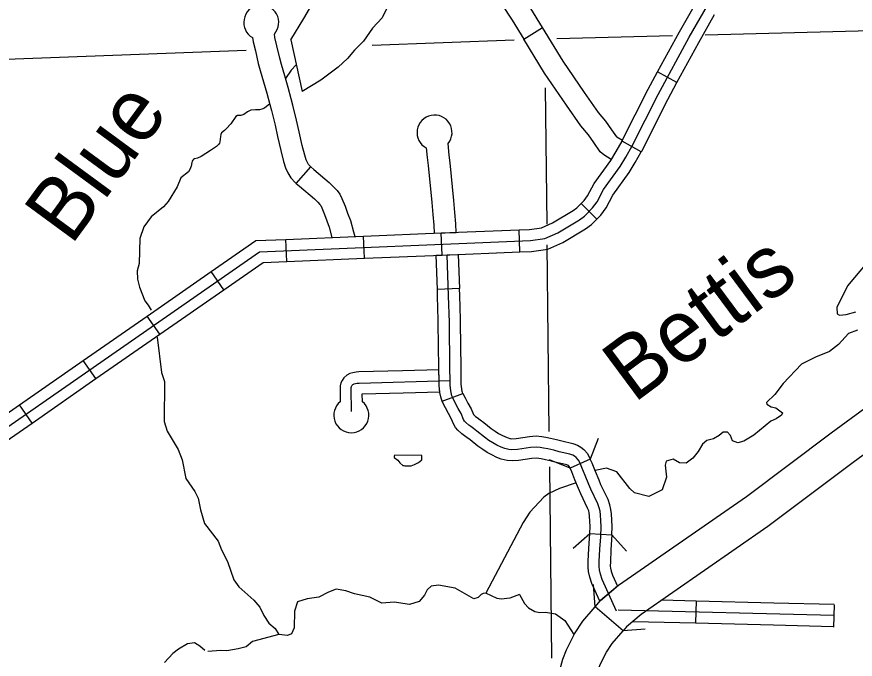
# Model space of a CAD drawing. Extents: x 1212896 to 1368412, y 378476 to 478763.
# Drawn here: x 1260272 to 1265961, y 391011 to 395366 of the extents above; entities that cross this region are included whole.
import ezdxf

# ---------------------------------------------------------------- set-up
doc = ezdxf.new("R2010")
doc.units = 0
for name, color, linetype in [('Level 10', 7, 'Continuous'), ('Level 31', 7, 'Continuous'), ('Level 32', 7, 'Continuous'), ('Level 35', 7, 'Continuous'), ('Level 37', 7, 'Continuous'), ('Level 38', 7, 'Continuous'), ('Level 45', 7, 'Continuous'), ('Level 5', 7, 'Continuous')]:
    doc.layers.add(name, color=color, linetype=linetype)

msp = doc.modelspace()

# ---------------------------------------------------------------- linework, layer by layer
at = {"layer": 'Level 10'}
msp.add_line((1264386.4, 391203.7), (1264196.6, 391366.5), dxfattribs=at)
for points in [[(1264196.6, 391366.5), (1264233, 391408.6), (1264354.8, 391512.8), (1265222.9, 392114.5), (1265798, 392544.8), (1267016.5, 393438.5), (1267604.8, 393882.3), (1267943.6, 394159.6), (1268436, 394612.2), (1271341.9, 397349.4)], [(1271515.3, 397169.3), (1268606.3, 394429.2), (1268107.5, 393970.7), (1267759.3, 393685.7), (1267165.7, 393237.9), (1265946.8, 392343.9), (1265369, 391911.6), (1264507.7, 391314.5), (1264409.8, 391230.9), (1264385.8, 391203)], [(1263932.2, 390847.3), (1263977.1, 391010.2), (1264001.5, 391075.5), (1264056.8, 391183.9), (1264112.6, 391269.3), (1264196.6, 391366.5)], [(1264173.2, 390780.7), (1264215.2, 390933.1), (1264230.7, 390974.8), (1264273.4, 391058.3), (1264312.7, 391118.5), (1264386.4, 391203.7)]]:
    msp.add_lwpolyline(points, dxfattribs=at)
at = {"layer": 'Level 31'}
for p, q in [((1263712.3, 395214.3), (1263840.2, 395292.6)), ((1263840.2, 395292.6), (1263840.2, 395292.6)), ((1262167.7, 394236.1), (1262266.5, 394348.9)), ((1262266.5, 394348.9), (1262266.5, 394348.9)), ((1263103.3, 393898.6), (1263253.2, 393904.7)), ((1263158.9, 392759.3), (1263299.5, 392811.5)), ((1263617.8, 392507.3), (1263617.8, 392507.3)), ((1264163.2, 392367.6), (1264025.9, 392307.2))]:
    msp.add_line(p, q, dxfattribs=at)
for points in [[(1263840.2, 395292.6), (1263760.1, 395423.5), (1263554.8, 395739.1)], [(1263428.3, 395658.4), (1263633.2, 395343.5), (1263712.3, 395214.3)], [(1262134.1, 394810.6), (1262113.4, 394887.5), (1262090.7, 394966.8), (1262068.3, 395043.8), (1262056.1, 395086.5), (1262037.2, 395170.2), (1262023.3, 395225.7), (1262019.5, 395249.2)], [(1264125.1, 394853), (1263979.4, 395065.1), (1263840.2, 395292.6)], [(1261871.5, 395224.8), (1261876.2, 395195.5), (1261891.2, 395135.5), (1261910.7, 395049.3), (1261924.2, 395002.2), (1261946.6, 394925.2), (1261968.9, 394847.3), (1261989.3, 394771.5)], [(1264001.5, 394768.1), (1263853.5, 394983.4), (1263712.3, 395214.3)], [(1264380.9, 394527.3), (1264344.2, 394551.2), (1264342.7, 394552.4), (1264310, 394600.7), (1264268.6, 394657.5), (1264218, 394717.8), (1264125.1, 394853)], [(1262266.5, 394348.9), (1262265, 394350.3), (1262252.1, 394364.1), (1262244.2, 394377.4), (1262236.2, 394395.5), (1262225.3, 394428.2), (1262208.7, 394493.4), (1262188.1, 394586.9), (1262170.3, 394666.3), (1262145.8, 394767.3), (1262134.1, 394810.6)], [(1261989.3, 394771.5), (1262000.5, 394730.1), (1262024.2, 394632.2), (1262041.6, 394554.4), (1262062.7, 394458.7), (1262081.3, 394385.9), (1262096.1, 394341.7), (1262110.6, 394308.5), (1262131.5, 394273.6), (1262160.3, 394242.5), (1262167.7, 394236.1)], [(1264305, 394397.7), (1264254.9, 394430.3), (1264230.4, 394450.7), (1264187.2, 394514.4), (1264150.4, 394565.1), (1264098.5, 394626.9), (1264001.5, 394768.1)], [(1263244.6, 394039), (1263237.9, 394121.5), (1263212.6, 394375.5), (1263205.1, 394427.8), (1263198.8, 394506.9)], [(1263050.7, 394477), (1263056, 394411.2), (1263063.7, 394357.4), (1263088.5, 394108), (1263095.1, 394026.9)], [(1262266.5, 394348.9), (1262287.2, 394330.8), (1262390.8, 394243.3), (1262421.4, 394214.5), (1262445.9, 394188), (1262463.2, 394163.2), (1262477.8, 394134), (1262500.4, 394081.8), (1262517, 394035.2), (1262535.9, 393985.4), (1262555.6, 393908.1), (1262565.7, 393876.5)], [(1262167.7, 394236.1), (1262189.4, 394217.1), (1262290.9, 394131.3), (1262314.8, 394108.9), (1262328.8, 394093.7), (1262333.9, 394086.3), (1262341.8, 394070.6), (1262360.8, 394026.7), (1262376.2, 393983.4), (1262392.6, 393940.2), (1262410.5, 393870.1)], [(1263095.1, 394026.9), (1263101.1, 393952.9), (1263103.3, 393898.6)], [(1263253.2, 393904.7), (1263250.9, 393962), (1263244.6, 394039)], [(1263117.5, 393749), (1263267.3, 393755.2)], [(1263125.6, 393517.5), (1263117.5, 393749)], [(1264341.6, 391337.1), (1264244.6, 391552.3), (1264232.5, 391587.8), (1264226.3, 391616.9), (1264224, 391638.9), (1264224.7, 391672.8), (1264227.9, 391757.5), (1264234, 391839.9), (1264236.8, 391911.6), (1264235.4, 391949.2), (1264232.5, 391989.7), (1264229.7, 392014.5), (1264224.7, 392037.1), (1264214.8, 392064.3), (1264167.3, 392163.3), (1264153.8, 392195.6), (1264128.9, 392256), (1264106.6, 392310.3), (1264093.8, 392339.1), (1264082.6, 392361.4), (1264067.2, 392378.1), (1264056.6, 392386.6), (1264045.2, 392393.7), (1264023.9, 392400.1), (1263953, 392417.9), (1263916.8, 392427.1), (1263876.3, 392436.3), (1263845.8, 392442.7), (1263823.8, 392447), (1263796.8, 392449.3), (1263758.5, 392446.3), (1263669.1, 392433.5), (1263631.5, 392430.7), (1263610, 392431.7), (1263582.5, 392439.2), (1263557.7, 392448.4), (1263528.6, 392462.6), (1263502.4, 392476.8), (1263475.4, 392493.9), (1263444.9, 392515.9), (1263394.5, 392556.3), (1263371.8, 392574.8), (1263353.3, 392587.6), (1263338.6, 392597.9), (1263317.9, 392615.5), (1263310.8, 392624.5), (1263303.5, 392636.2), (1263286.6, 392675.6), (1263266.8, 392711.3), (1263247.6, 392748.1), (1263230, 392783.2), (1263224.9, 392797.1), (1263222.1, 392807.2), (1263217.3, 392831.1), (1263212.8, 392869.5), (1263212.1, 392900), (1263211.4, 392983.8), (1263207.2, 393292.7), (1263202.2, 393473.8), (1263192.4, 393752.1)], [(1263267.3, 393755.2), (1263275.5, 393523.7)], [(1263275.5, 393523.7), (1263125.6, 393517.5)], [(1263131.7, 393309.4), (1263127.2, 393471.4), (1263125.6, 393517.5)], [(1263281.6, 393313.5), (1263277.2, 393476.1), (1263275.5, 393523.7)], [(1263158.9, 392759.3), (1263153.5, 392773.8), (1263149.1, 392789.7), (1263143.1, 392819.5), (1263137.9, 392864.3), (1263137.1, 392898.8), (1263136.4, 392983), (1263132.2, 393291.2), (1263131.7, 393309.4)], [(1263299.5, 392811.5), (1263296.3, 392820.3), (1263295, 392824.7), (1263291.4, 392842.8), (1263287.7, 392874.7), (1263287.1, 392901.2), (1263286.4, 392984.6), (1263282.1, 393294.2), (1263281.6, 393313.5)], [(1262889.2, 392966.4), (1262592.4, 392958.4), (1262573.7, 392957), (1262551.3, 392953.3), (1262532.5, 392947), (1262510.6, 392936.8), (1262490, 392918), (1262479.1, 392900.9), (1262471.3, 392884.2), (1262466.7, 392863.9), (1262465.8, 392844.8), (1262466.9, 392756.4)], [(1263136.5, 392973), (1262889.2, 392966.4)], [(1263142.7, 392823.1), (1263137.9, 392864.3), (1263137.1, 392898.8), (1263136.5, 392973)], [(1262542.6, 392689.5), (1262540.8, 392843.6), (1262541.3, 392853.8), (1262542.6, 392859.6), (1262545.1, 392864.8), (1262547.9, 392869.3), (1262552.8, 392873.7), (1262560.3, 392877.3), (1262569.4, 392880.3), (1262582.6, 392882.5), (1262596.1, 392883.4), (1263212.1, 392900)], [(1262616.9, 392756.5), (1262616.3, 392809), (1262893.3, 392816.4)], [(1262893.3, 392816.4), (1263142.7, 392823.1)], [(1263299.5, 392811.5), (1263314.4, 392782.2), (1263332.8, 392746.9), (1263354.1, 392708.7), (1263370.2, 392670.9), (1263372.2, 392667.7), (1263384.4, 392657.4), (1263396.2, 392649.1), (1263416.9, 392634.8), (1263441.6, 392614.7), (1263490.3, 392575.6), (1263517.4, 392556), (1263540.3, 392541.6), (1263562.9, 392529.3), (1263587.3, 392517.4), (1263605.5, 392510.7), (1263617.8, 392507.3)], [(1263578.5, 392362.6), (1263559.6, 392367.7), (1263528.1, 392379.4), (1263494.3, 392395.9), (1263464.4, 392412.1), (1263433.4, 392431.7), (1263399.4, 392456.2), (1263347.3, 392498), (1263326.7, 392514.8), (1263310.5, 392526), (1263292.8, 392538.4), (1263263.5, 392563.2), (1263249.2, 392581.5), (1263236.8, 392601.5), (1263219.2, 392642.6), (1263200.7, 392675.7), (1263180.8, 392714), (1263161.1, 392753.3), (1263158.9, 392759.3)], [(1263617.8, 392507.3), (1263621.8, 392506.2), (1263630.5, 392505.8), (1263661, 392508.1), (1263750.3, 392520.9), (1263797.1, 392524.5), (1263834.2, 392521.4), (1263860.6, 392516.2), (1263892.4, 392509.6), (1263934.4, 392500), (1263971.3, 392490.6), (1264043.8, 392472.5), (1264076.4, 392462.7), (1264100, 392447.9), (1264118.5, 392433.2), (1264145, 392404.5), (1264163.2, 392367.6)], [(1264025.9, 392307.2), (1264020.3, 392318.3), (1264016, 392323.1), (1264013.7, 392324.9), (1264004, 392327.8), (1263934.6, 392345.2), (1263899.2, 392354.2), (1263860.3, 392363.1), (1263831, 392369.2), (1263813.5, 392372.6), (1263796.6, 392374), (1263766.8, 392371.7), (1263677.3, 392358.9), (1263632.5, 392355.5), (1263598.2, 392357.2), (1263578.5, 392362.6)], [(1264309.6, 391854.7), (1264311.9, 391911.5), (1264310.3, 391953.3), (1264307.2, 391996.6), (1264303.8, 392026.9), (1264296.9, 392058.1), (1264284, 392093.4), (1264235.7, 392194), (1264223.1, 392224.3), (1264198.3, 392284.5), (1264175.5, 392339.8), (1264163.2, 392367.6)], [(1264159.8, 391863.2), (1264161.7, 391911.8), (1264160.4, 391945.3), (1264157.8, 391983), (1264155.5, 392002.4), (1264152.5, 392016.2), (1264145.5, 392035.2), (1264098.7, 392132.8), (1264084.4, 392167.1), (1264059.5, 392227.6), (1264037.5, 392281), (1264025.9, 392307.2)], [(1264229.1, 391404.1), (1264174.8, 391524.7), (1264160.1, 391567.8), (1264152.2, 391605.1), (1264148.9, 391635.8), (1264149.8, 391675), (1264153, 391761.6), (1264159.8, 391863.2)], [(1264159.8, 391863.2), (1264309.6, 391854.7)], [(1264309.6, 391854.7), (1264302.8, 391753.3), (1264299.7, 391670.6), (1264299.1, 391642), (1264300.5, 391628.7), (1264305, 391607.7), (1264314.5, 391579.8), (1264347.5, 391506.5)], [(1264347.5, 391506.5), (1264233, 391408.6), (1264229.1, 391404.1)]]:
    msp.add_lwpolyline(points, dxfattribs=at)
for centre, start, end in [((1261930.5, 395327.7), 318.5685, 240.1612), ((1263106.6, 394581.7), 320.9445, 241.8735), ((1262542, 392664.5), 129.2679, 50.856)]:
    msp.add_arc(centre, 118.7, start, end, dxfattribs=at)
at = {"layer": 'Level 32'}
for p, q in [((1264751.3, 394920.4), (1264619.6, 394992.1)), ((1264509.5, 394449.8), (1264378.9, 394523.5)), ((1264207.6, 393994.9), (1264101.2, 394100.7)), ((1262630.7, 393729), (1262624.6, 393878.9)), ((1263158.3, 393750.7), (1263152.1, 393900.6)), ((1263685.8, 393772.4), (1263679.7, 393922.2)), ((1262103.2, 393707.4), (1262097, 393857.2)), ((1261676.3, 393515.1), (1261590.7, 393638.3)), ((1261242.5, 393214), (1261157, 393337.2)), ((1260808.8, 392912.9), (1260723.3, 393036.1)), ((1260375.1, 392611.8), (1260289.5, 392735))]:
    msp.add_line(p, q, dxfattribs=at)
for points in [[(1259971.3, 392421.1), (1261919.5, 393773.5), (1263757.6, 393849), (1263854.1, 393862.3), (1263943, 393901.2), (1264089.6, 393988.6), (1264123.1, 394014.3), (1264179.1, 394070.7), (1264209.7, 394110.8), (1264253.9, 394195.4), (1264365.6, 394350.5), (1264405.3, 394415), (1264447.9, 394490.5), (1264623.2, 394839), (1264835.1, 395227.9), (1264983.4, 395488.6)], [(1264619.6, 394992.1), (1264768.4, 395265.1), (1264876.4, 395455)], [(1264751.3, 394920.4), (1264899.4, 395192.1), (1265006.8, 395380.9)], [(1264378.9, 394523.5), (1264380.5, 394526.4), (1264555.5, 394874.5), (1264619.6, 394992.1)], [(1264509.5, 394449.8), (1264512.9, 394455.9), (1264688.4, 394804.9), (1264751.3, 394920.4)], [(1264101.2, 394100.7), (1264121.4, 394121), (1264145, 394151.9), (1264188.7, 394235.6), (1264302, 394392.9), (1264339.5, 394453.7), (1264378.9, 394523.5)], [(1264207.6, 393994.9), (1264234.7, 394022.2), (1264272.1, 394071.1), (1264316.7, 394156.7), (1264426.9, 394309.6), (1264468.7, 394377.6), (1264509.5, 394449.8)], [(1263679.7, 393922.2), (1263750.8, 393925.2), (1263833.2, 393936.5), (1263907.9, 393969.2), (1264046.6, 394052), (1264072.5, 394071.8), (1264101.2, 394100.7)], [(1263685.8, 393772.4), (1263764.1, 393775.6), (1263874.3, 393790.7), (1263976.7, 393835.6), (1264130.9, 393927.6), (1264171.8, 393958.9), (1264207.6, 393994.9)], [(1262097, 393857.2), (1262624.6, 393878.9)], [(1262624.6, 393878.9), (1263152.1, 393900.6)], [(1263152.1, 393900.6), (1263679.7, 393922.2)], [(1261590.7, 393638.3), (1261894.2, 393848.9), (1262097, 393857.2)], [(1263158.3, 393750.7), (1263685.8, 393772.4)], [(1261676.3, 393515.1), (1261943.9, 393700.8), (1262103.2, 393707.4)], [(1262103.2, 393707.4), (1262630.7, 393729)], [(1262630.7, 393729), (1263158.3, 393750.7)], [(1261157, 393337.2), (1261590.7, 393638.3)], [(1261242.5, 393214), (1261676.3, 393515.1)], [(1260723.3, 393036.1), (1261157, 393337.2)], [(1260808.8, 392912.9), (1261242.5, 393214)], [(1260289.5, 392735), (1260723.3, 393036.1)], [(1260375.1, 392611.8), (1260808.8, 392912.9)], [(1259879.5, 392450.8), (1259884.7, 392452.1), (1259907.3, 392467.9), (1259925.7, 392482.5), (1260289.5, 392735)], [(1259914.5, 392305), (1259947.4, 392312.8), (1259996.9, 392347.5), (1260015.2, 392361.9), (1260375.1, 392611.8)]]:
    msp.add_lwpolyline(points, dxfattribs=at)
at = {"layer": 'Level 35'}
for points in [[(1262131.3, 395210.5), (1262220.5, 395355), (1262273.2, 395447.3), (1262334.7, 395667), (1262536.7, 395750.5), (1262576.2, 395737.3), (1262607, 395728.5), (1262642.1, 395746.1), (1262729.9, 395772.5), (1262809, 395798.8), (1262839.7, 395825.2), (1262861.7, 395856), (1262927.6, 395917.5), (1262971.5, 395965.8), (1262997.8, 395987.8), (1263028.6, 395996.6), (1263072.3, 395991.4), (1263098.4, 395983.4)], [(1263252.1, 395680.2), (1263244.1, 395664.5), (1263223.9, 395649.3), (1263182.3, 395627.5), (1263085.6, 395601.1), (1263024.2, 395587.9), (1262962.7, 395548.4), (1262901.2, 395517.6), (1262817.8, 395469.3), (1262787, 395434.1), (1262751.9, 395359.4), (1262686, 395289.1), (1262624.5, 395201.2), (1262563.1, 395139.7), (1262514.8, 395082.6), (1262453.3, 395025.4), (1262334.7, 394937.5), (1262207.4, 394858.9)], [(1262131.3, 395210.5), (1262207.4, 394858.9)], [(1262167.9, 395041.2), (1262134.1, 395005.3), (1262096.3, 394947.3)], [(1261988.3, 394775.2), (1261952, 394745.7), (1261935.2, 394740.1), (1261918.7, 394736.2), (1261892.5, 394736.2), (1261859.7, 394733.6), (1261837.9, 394721.1), (1261813.5, 394703.7), (1261792.3, 394697.1), (1261770.6, 394696.1), (1261758.1, 394689.5), (1261723.5, 394640.9), (1261692.6, 394607.6), (1261680.7, 394595.7), (1261661.6, 394579), (1261657, 394567.7), (1261654.5, 394555.2), (1261652.1, 394536.1), (1261649.7, 394519.5), (1261646.7, 394509.6), (1261641.2, 394500.3), (1261625.9, 394486.1), (1261585.5, 394459.9), (1261523.3, 394419.8), (1261497.4, 394407.5), (1261478.2, 394404.1), (1261471.7, 394399.7), (1261466.8, 394394.8), (1261462.5, 394386.7), (1261459.2, 394377.4), (1261454.3, 394352.4), (1261446.2, 394330.7), (1261436.8, 394314.4)], [(1261436.8, 394314.4), (1261385.8, 394274.3), (1261359.8, 394214.3), (1261299.1, 394115), (1261268.4, 394077.9), (1261182.7, 394008.9), (1261133, 393941.1), (1261105.7, 393862), (1261101.4, 393692.6), (1261089, 393644.1), (1261090.9, 393587.1), (1261104.7, 393532.4), (1261139.8, 393440.5), (1261163.8, 393410.2), (1261182.9, 393376.8)], [(1266039.4, 393697.8), (1265908.6, 393542.1), (1265835.5, 393396.4), (1265839, 393353.5), (1265854.3, 393343), (1265899.1, 393348.5), (1265964.5, 393366.7)], [(1261225.1, 393194.3), (1261253.1, 392954.5), (1261273.1, 392894.1), (1261271.2, 392623.5), (1261291.5, 392556.1), (1261366.6, 392433.4), (1261395, 392362.3), (1261419.2, 392236.9), (1261480.2, 392146.8), (1261502.7, 392102.5), (1261518.3, 392022.9), (1261546.4, 391930.7), (1261638.5, 391810.6), (1261660.4, 391753.2), (1261701, 391673.5), (1261745.2, 391548.8), (1261778.8, 391500.8), (1261879.8, 391412.1), (1261920.4, 391364.4), (1261947.3, 391307.2), (1261982, 391255.3), (1262024.2, 391219.7), (1262049.6, 391179.5)], [(1265976.7, 393240.9), (1265915.8, 393219.4), (1265847, 393144.4), (1265786.6, 393097.2), (1265690.9, 393058.9), (1265597.5, 393011.7), (1265473, 392879.2), (1265415.4, 392806.1)], [(1265415.4, 392806.1), (1265359.3, 392751.1), (1265360.7, 392740.2), (1265390.3, 392722.1), (1265421.5, 392714.2), (1265466.6, 392681.7), (1265461.2, 392665.5), (1265425, 392640.2), (1265387.6, 392623.9), (1265272.8, 392529.8), (1265205.9, 392490.1), (1265165.5, 392478.1), (1265128.1, 392491.9), (1265115.8, 392528.5), (1265095.3, 392549.7), (1265065.1, 392549.8), (1265036.9, 392526.8), (1264998.6, 392505.5), (1264953.1, 392492.9), (1264924.9, 392468.9), (1264894.6, 392418.8), (1264858.1, 392373.5), (1264813.3, 392340.1), (1264769.1, 392342.4), (1264726.4, 392366), (1264678.8, 392354.4), (1264670.7, 392326.1), (1264681.4, 392245.3), (1264650.4, 392158.1), (1264559.9, 392113.9), (1264463, 392139.7), (1264431, 392168.7), (1264344.3, 392280.9), (1264272.4, 392306.5), (1264195.5, 392291.2)], [(1263021.1, 392391.3), (1262835.3, 392394.2), (1262833.7, 392391), (1262832.8, 392387.3), (1262832.4, 392382.3), (1262833.5, 392378.1), (1262856.6, 392360), (1262871.3, 392343.1), (1262891.6, 392325.2), (1262897.3, 392323.4), (1262904.5, 392322.7), (1262947.1, 392322.6), (1262959.9, 392325.9), (1262970.9, 392330.5), (1262984, 392336.8), (1262998.1, 392345), (1263021.1, 392362.2), (1263021.1, 392391.3)], [(1264068, 392206.9), (1263954.2, 392167.5), (1263882.3, 392134), (1263848.2, 392108.8), (1263753.6, 392008.4), (1263709, 391936.8), (1263454.9, 391459.6)], [(1263682.2, 391450.3), (1263682.2, 391450.3), (1263618, 391425.1), (1263558.3, 391418.1), (1263531.1, 391422.1), (1263454.9, 391459.6), (1263436, 391457), (1263422.2, 391449.5), (1263402.9, 391428.8), (1263374.2, 391419.8), (1263246.9, 391491.6), (1263133.1, 391513.8), (1263083.4, 391507.1), (1263057.2, 391482.2), (1263038.5, 391444.5), (1263001.9, 391402.2), (1262937.6, 391382.9), (1262833.1, 391397.4), (1262748.3, 391390.5), (1262667, 391430.8), (1262563.3, 391453.4), (1262505.7, 391475.5), (1262439.4, 391485.3), (1262387.8, 391465.6), (1262320.8, 391431.2), (1262242.5, 391419.4), (1262176.1, 391400.1), (1262155.3, 391336.3), (1262155, 391224.1), (1262136.5, 391182.4), (1262109.8, 391171.5), (1262049.6, 391179.5), (1261872.3, 391130.4), (1261827.5, 391094.8), (1261773.9, 391080.9), (1261696.4, 391068.3), (1261655.3, 391069.9), (1261567.2, 391062.1)], [(1263682.2, 391450.3), (1263717.2, 391388.4), (1263745.2, 391358.3), (1263787.1, 391333.7), (1263821.3, 391326.8), (1263859.2, 391329.1), (1263927.9, 391318.7), (1263990, 391273.5), (1264051.2, 391179.4), (1264054, 391175.7)], [(1261548.3, 391070.3), (1261514.4, 391100.2), (1261476.6, 391122.9), (1261430.8, 391115.4), (1261368.1, 391078.2), (1261331.1, 391049.9), (1261275.1, 390988.9)]]:
    msp.add_lwpolyline(points, dxfattribs=at)
at = {"layer": 'Level 37'}
for points in [[(1264196.9, 391366.8), (1264185.9, 391516.4)], [(1264535.7, 391214.3), (1264386.1, 391203.4)]]:
    msp.add_lwpolyline(points, dxfattribs=at)
at = {"layer": 'Level 38'}
for points in [[(1264217.6, 392507.4), (1264163.2, 392367.6)], [(1264025.9, 392307.2), (1263886.1, 392361.6)], [(1264048, 391763.2), (1264159.8, 391863.2)], [(1264309.6, 391854.7), (1264409.5, 391742.9)]]:
    msp.add_lwpolyline(points, dxfattribs=at)
at = {"layer": 'Level 45'}
for p, q in [((1264882.1, 391406.6), (1264878.3, 391256.6)), ((1265817.7, 391378.7), (1265813.9, 391228.8))]:
    msp.add_line(p, q, dxfattribs=at)
for points in [[(1264648.9, 391412.4), (1264882.1, 391406.6)], [(1264882.1, 391406.6), (1265409.9, 391393.3)], [(1265409.9, 391393.3), (1265817.3, 391383)], [(1264352.4, 391346.2), (1265815.5, 391309.4)], [(1264452.4, 391267.3), (1264878.3, 391256.6)], [(1264878.3, 391256.6), (1265406.1, 391243.3)], [(1265406.1, 391243.3), (1265813.6, 391233.1)]]:
    msp.add_lwpolyline(points, dxfattribs=at)
at = {"layer": 'Level 5'}
for points in [[(1271746.1, 395342.8), (1269185.1, 395351.7), (1264943.5, 395242.6)], [(1263647.5, 395206.9), (1262682.9, 395170.8)], [(1264722.1, 395236.9), (1263935.5, 395216.7)], [(1261827.8, 395138.7), (1258629.3, 395019), (1257400.3, 394985.6)], [(1263869.7, 393960.3), (1263859.4, 394884.6)], [(1263885.3, 392553.6), (1263871.2, 393820.5)], [(1263902.3, 391017.6), (1263887.9, 392314.3)]]:
    msp.add_lwpolyline(points, dxfattribs=at)

# ---------------------------------------------------------------- texts
at = {"layer": 'Level 35'}
for s, rotation, p in [('Blue', 53.738, (1260640.5, 393809.4)), ('Bettis', 36.6132, (1264458.2, 392742.2))]:
    msp.add_text(s, height=422.4, rotation=rotation, dxfattribs=at).set_placement(p)

doc.saveas('drawing.dxf')
